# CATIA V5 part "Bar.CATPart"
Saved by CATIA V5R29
Part number: Bar
Source: Unknown
Bounding box of the stored display mesh (mm): x 0 to 558, y -40 to 40, z -30 to 30
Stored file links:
  C:\가치같이\SmartFactory_BoxErectorConveyor\Boxing(over)\Bar.CATPart
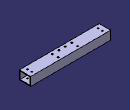
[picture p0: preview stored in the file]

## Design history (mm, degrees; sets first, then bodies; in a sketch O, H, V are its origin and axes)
Body1 (main body)
  Solid1 "PartBody": solid without history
